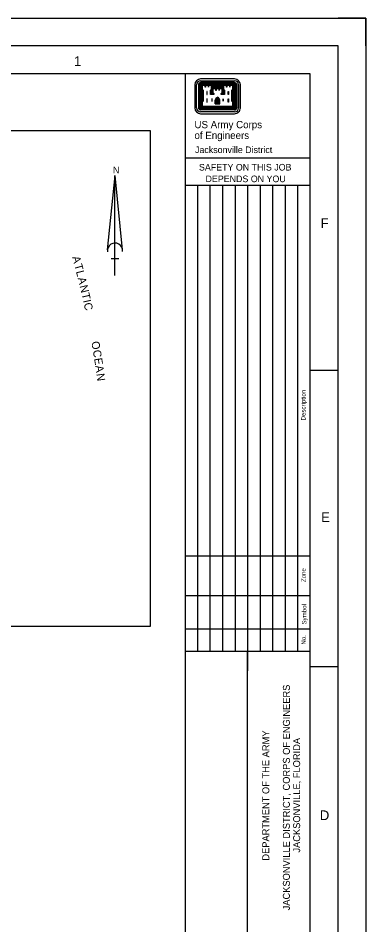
# Model space of a CAD drawing. Extents: x 452225 to 584229, y 1232161 to 1334160.
# Drawn here: x 565476 to 584225, y 1285243 to 1334160 of the extents above; entities that cross this region are included whole.
import ezdxf

# ---------------------------------------------------------------- set-up
doc = ezdxf.new("R2010")
doc.units = 0
for name, color, linetype in [('G-ANNO-NPLT', 7, 'Continuous'), ('G-ANNO-TEXT-LOGO', 7, 'Continuous'), ('G-ANNO-TEXT-TTLB', 7, 'Continuous'), ('G-ANNO-TTLB', 7, 'Continuous'), ('V-ANNO-SYMB', 7, 'Continuous')]:
    doc.layers.add(name, color=color, linetype=linetype)

msp = doc.modelspace()

# ---------------------------------------------------------------- linework, layer by layer
at = {"layer": 'G-ANNO-NPLT'}
msp.add_lwpolyline([(452225, 1334160), (584225, 1334160), (584225, 1232161), (452225, 1232161)], close=True, dxfattribs=at)
msp.add_lwpolyline([(584225, 1332660), (584225, 1334160), (582725, 1334160)], dxfattribs=at)
at = {"layer": 'G-ANNO-TEXT-LOGO'}
for p, q in [((577140, 1330879), (575316, 1330879)), ((575316, 1330783), (577140, 1330783)), ((577140, 1330681), (575316, 1330681)), ((577140, 1330654), (575316, 1330654)), ((577140, 1330627), (575316, 1330627)), ((577140, 1330603), (575316, 1330603)), ((577140, 1330576), (575316, 1330576)), ((574995, 1330558), (574995, 1329328)), ((575091, 1329328), (575091, 1330558)), ((575196, 1330558), (575196, 1329328)), ((575223, 1330558), (575223, 1329328)), ((575247, 1330558), (575247, 1329328)), ((575274, 1330558), (575274, 1329328)), ((575301, 1330558), (575301, 1329328)), ((575328, 1330558), (575328, 1329337)), ((575352, 1330558), (575352, 1329364)), ((575373, 1330297), (575373, 1329667)), ((575400, 1330270), (575400, 1329697)), ((575949, 1330552), (576507, 1330552)), ((575949, 1330525), (576507, 1330525)), ((575949, 1330501), (576507, 1330501)), ((575949, 1330474), (576507, 1330474)), ((575949, 1330447), (576507, 1330447)), ((575949, 1330423), (576507, 1330423)), ((575949, 1330396), (576507, 1330396)), ((577056, 1330270), (577056, 1329697)), ((577083, 1330294), (577083, 1329670)), ((577104, 1330558), (577104, 1329364)), ((577128, 1330558), (577128, 1329337)), ((577155, 1330558), (577155, 1329328)), ((577182, 1330558), (577182, 1329328)), ((577206, 1330558), (577206, 1329328)), ((577233, 1330558), (577233, 1329328)), ((577260, 1330558), (577260, 1329328)), ((577362, 1330558), (577362, 1329328)), ((577461, 1329328), (577461, 1330558)), ((576108, 1329541), (576108, 1329742)), ((576132, 1329541), (576132, 1329742)), ((576159, 1329541), (576159, 1329742)), ((576186, 1329541), (576186, 1329742)), ((576210, 1329541), (576210, 1329742)), ((576246, 1329541), (576246, 1329742)), ((576270, 1329541), (576270, 1329742)), ((576297, 1329541), (576297, 1329742)), ((576324, 1329541), (576324, 1329742)), ((576348, 1329541), (576348, 1329742)), ((577140, 1329310), (575316, 1329310)), ((577140, 1329286), (575316, 1329286)), ((577140, 1329259), (575316, 1329259)), ((577140, 1329232), (575316, 1329232)), ((577140, 1329208), (575316, 1329208)), ((577140, 1329103), (575316, 1329103)), ((577128, 1329337), (575328, 1329337)), ((577104, 1329364), (575352, 1329364)), ((576108, 1329541), (576348, 1329541)), ((575316, 1329004), (577140, 1329004))]:
    msp.add_line(p, q, dxfattribs=at)
for points in [[(575373, 1330558), (575373, 1330321), (575424, 1330270), (575424, 1329697), (575373, 1329643), (575373, 1329382), (577083, 1329382), (577083, 1329643), (577029, 1329697), (577029, 1330270), (577083, 1330321), (577083, 1330558), (576858, 1330558), (576684, 1330558), (576522, 1330558), (576522, 1330321), (576579, 1330270), (576579, 1330060), (576453, 1330060), (576453, 1330081), (576507, 1330135), (576507, 1330369), (576282, 1330369), (576108, 1330369), (575949, 1330369), (575949, 1330135), (576003, 1330081), (576003, 1330060), (575877, 1330060), (575877, 1330270), (575931, 1330321), (575931, 1330558), (575706, 1330558), (575532, 1330558), (575373, 1330558)], [(575397, 1330531), (575397, 1330333), (575451, 1330279), (575451, 1329685), (575397, 1329631), (575397, 1329409), (577059, 1329409), (577059, 1329631), (577002, 1329685), (577002, 1330279), (577059, 1330333), (577059, 1330531), (576897, 1330531), (576897, 1330438), (576882, 1330438), (576882, 1330531), (576723, 1330531), (576723, 1330438), (576711, 1330438), (576711, 1330531), (576549, 1330531), (576549, 1330333), (576603, 1330279), (576603, 1330036), (576429, 1330036), (576429, 1330093), (576483, 1330147), (576483, 1330345), (576321, 1330345), (576321, 1330252), (576309, 1330252), (576309, 1330345), (576147, 1330345), (576147, 1330252), (576132, 1330252), (576132, 1330345), (575973, 1330345), (575973, 1330147), (576027, 1330093), (576027, 1330036), (575853, 1330036), (575853, 1330279), (575907, 1330333), (575907, 1330531), (575748, 1330531), (575748, 1330438), (575733, 1330438), (575733, 1330531), (575571, 1330531), (575571, 1330438), (575559, 1330438), (575559, 1330531), (575397, 1330531)], [(575643, 1330210), (575643, 1330036), (575661, 1330036), (575661, 1330210), (575643, 1330210)], [(575919, 1330273), (575904, 1330258), (575904, 1330087), (575961, 1330087), (575922, 1330126), (575922, 1330276)], [(576537, 1330273), (576552, 1330258), (576552, 1330087), (576498, 1330087), (576534, 1330126), (576534, 1330276)], [(576810, 1330210), (576810, 1330036), (576795, 1330036), (576795, 1330210), (576810, 1330210)], [(575643, 1329811), (575643, 1329634), (575661, 1329634), (575661, 1329811), (575643, 1329811)], [(575919, 1329811), (575919, 1329688), (575934, 1329688), (575934, 1329811), (575919, 1329811)], [(576537, 1329811), (576537, 1329688), (576522, 1329688), (576522, 1329811), (576537, 1329811)], [(576810, 1329811), (576810, 1329634), (576795, 1329634), (576795, 1329811), (576810, 1329811)]]:
    msp.add_lwpolyline(points, dxfattribs=at)
for centre, major_axis, start_param, end_param in [((575317, 1330558), (321, 0), 1.57078, 3.141576), ((575317, 1330558), (225, 0), 1.57078, 3.141576), ((575317, 1330558), (121, 0), 1.57078, 3.141576), ((575317, 1330558), (94.5, 0), 1.57078, 3.141576), ((575317, 1330558), (68.4, 0), 1.57078, 3.141576), ((575317, 1330558), (42.4, 0), 1.57078, 3.141576), ((575317, 1330558), (16.4, 0), 1.57078, 3.141576), ((577139, 1330558), (321, 0), 6.283169, 7.853965), ((577139, 1330558), (225, 0), 6.28317, 7.853966), ((577139, 1330558), (121, 0), 6.283169, 7.853965), ((577139, 1330558), (94.5, 0), 6.283169, 7.853965), ((577139, 1330558), (68.4, 0), 6.283169, 7.853965), ((577139, 1330558), (42.4, 0), 6.283169, 7.853965), ((577139, 1330558), (16.4, 0), 6.283169, 7.853965), ((576273, 1329728), (-167, 0), 4.985832, 6.214359), ((576273, 1329728), (-141, 0), 4.947465, 6.21436), ((576273, 1329728), (-115, 0), 4.947465, 6.21436), ((576273, 1329728), (-88.5, 0), 4.947465, 6.21436), ((576183, 1329728), (62.4, 0), 0.068794, 1.335689), ((576183, 1329728), (88.5, 0), 0.068794, 1.335689), ((576183, 1329728), (115, 0), 0.068795, 1.335689), ((576273, 1329728), (-62.4, 0), 4.947465, 6.214359), ((576183, 1329728), (141, 0), 0.068795, 1.335689), ((576183, 1329728), (167, 0), 0.068795, 1.29842), ((575317, 1329327), (-321, 0), 6.28317, 7.853966), ((575317, 1329327), (-225, 0), 6.28317, 7.853966), ((575317, 1329327), (-121, 0), 6.28317, 7.853966), ((575317, 1329327), (-94.5, 0), 6.28317, 7.853966), ((575317, 1329327), (-68.4, 0), 6.28317, 7.853966), ((575317, 1329327), (-42.4, 0), 6.28317, 7.853966), ((575317, 1329327), (-16.4, 0), 6.28317, 7.853966), ((577139, 1329327), (121, 0), 4.712373, 6.28317), ((577139, 1329327), (94.5, 0), 4.712373, 6.28317), ((577139, 1329327), (68.4, 0), 4.712373, 6.28317), ((577139, 1329327), (42.4, 0), 4.712373, 6.28317), ((577139, 1329327), (16.4, 0), 4.712373, 6.28317), ((577139, 1329327), (321, 0), 4.712373, 6.28317), ((577139, 1329327), (-225, 0), 1.570781, 3.141577)]:
    msp.add_ellipse(centre, major_axis=major_axis, ratio=0.99964, start_param=start_param, end_param=end_param, dxfattribs=at)
at = {"layer": 'G-ANNO-TTLB'}
for p, q in [((574474, 1331160), (574474, 1235161)), ((574475, 1326623), (581225, 1326623)), ((574456, 1325150), (581206, 1325150)), ((575144, 1325150), (575144, 1300012)), ((575819, 1325150), (575819, 1300012)), ((576494, 1325150), (576494, 1300012)), ((577169, 1325150), (577169, 1300012)), ((577844, 1325150), (577844, 1300012)), ((578519, 1325150), (578519, 1300012)), ((579194, 1325150), (579194, 1300012)), ((579869, 1325150), (579869, 1300012)), ((580544, 1325150), (580544, 1300012)), ((582725, 1315155), (581225, 1315155)), ((574475, 1305143), (581225, 1305143)), ((574475, 1303008), (581225, 1303008)), ((574475, 1301208), (581225, 1301207)), ((574475, 1300012), (581225, 1300012)), ((577830, 1274225), (577850, 1300012)), ((577850, 1300012), (577849, 1298950)), ((582725, 1299156), (581225, 1299156))]:
    msp.add_line(p, q, dxfattribs=at)
for points in [[(453725, 1233661), (582725, 1233661), (582725, 1332660), (453725, 1332660)], [(581225, 1331160), (457475, 1331160), (457475, 1235161), (581225, 1235161)]]:
    msp.add_lwpolyline(points, close=True, dxfattribs=at)
at = {"layer": 'V-ANNO-SYMB'}
for p, q in [((572610, 1328089), (542976, 1328089)), ((572610, 1301350), (572610, 1328089)), ((570293, 1321662), (570710, 1325668)), ((570696, 1320270), (570696, 1325670)), ((571099, 1321659), (570707, 1325671)), ((570492, 1321201), (570897, 1321201)), ((542976, 1301350), (572610, 1301350))]:
    msp.add_line(p, q, dxfattribs=at)
msp.add_arc((570696, 1321620), 405, 353.3459, 188.7908, dxfattribs=at)

# ---------------------------------------------------------------- texts
at = {"layer": 'G-ANNO-TEXT-TTLB'}
for s, height, p in [('US Army Corps', 392.58, (574983, 1328221)), ('of Engineers', 392.58, (574983, 1327639)), ('Jacksonville District', 356.99, (575013, 1326880)), ('SAFETY ON THIS JOB', 357, (575227, 1325938)), ('DEPENDS ON YOU', 357, (575581, 1325311))]:
    msp.add_text(s, height=height, dxfattribs=at).set_placement(p)
for s, height, p in [('Description', 240, (580973, 1312454)), ('Zone', 240, (580982, 1303733)), ('Symbol', 240, (581017, 1301444)), ('No.', 240, (580987, 1300360)), ('JACKSONVILLE DISTRICT, CORPS OF ENGINEERS', 375, (580126, 1286026)), ('DEPARTMENT OF THE ARMY', 375, (579016, 1288708)), ('JACKSONVILLE, FLORIDA', 375, (580681, 1289142))]:
    msp.add_text(s, height=height, rotation=90, dxfattribs=at).set_placement(p)
at = {"layer": 'G-ANNO-TTLB'}
for s, p in [('1', (568487, 1331576)), ('F', (581788, 1322841)), ('E', (581812, 1306975)), ('D', (581745, 1290892))]:
    msp.add_text(s, height=525, dxfattribs=at).set_placement(p)
at = {"layer": 'V-ANNO-SYMB'}
for s, height, rotation, p in [('N', 354, 0, (570593, 1325789)), ('A', 432, 285.3188, (568381, 1321266)), ('T', 432, 284.8034, (568496, 1320846)), ('L', 432, 284.3674, (568590, 1320489)), ('A', 432, 283.9315, (568682, 1320132)), ('N', 432, 283.4161, (568787, 1319709)), ('T', 432, 282.9008, (568888, 1319285)), ('I', 432, 282.4648, (568971, 1318925)), ('C', 432, 282.2667, (569008, 1318762)), ('O', 432, 279.7701, (569420, 1316691)), ('C', 432, 279.215, (569500, 1316228)), ('E', 432, 278.6996, (569570, 1315798)), ('A', 432, 278.2236, (569631, 1315400)), ('N', 432, 277.7082, (569693, 1314968))]:
    msp.add_text(s, height=height, rotation=rotation, dxfattribs=at).set_placement(p)

doc.saveas('drawing.dxf')
